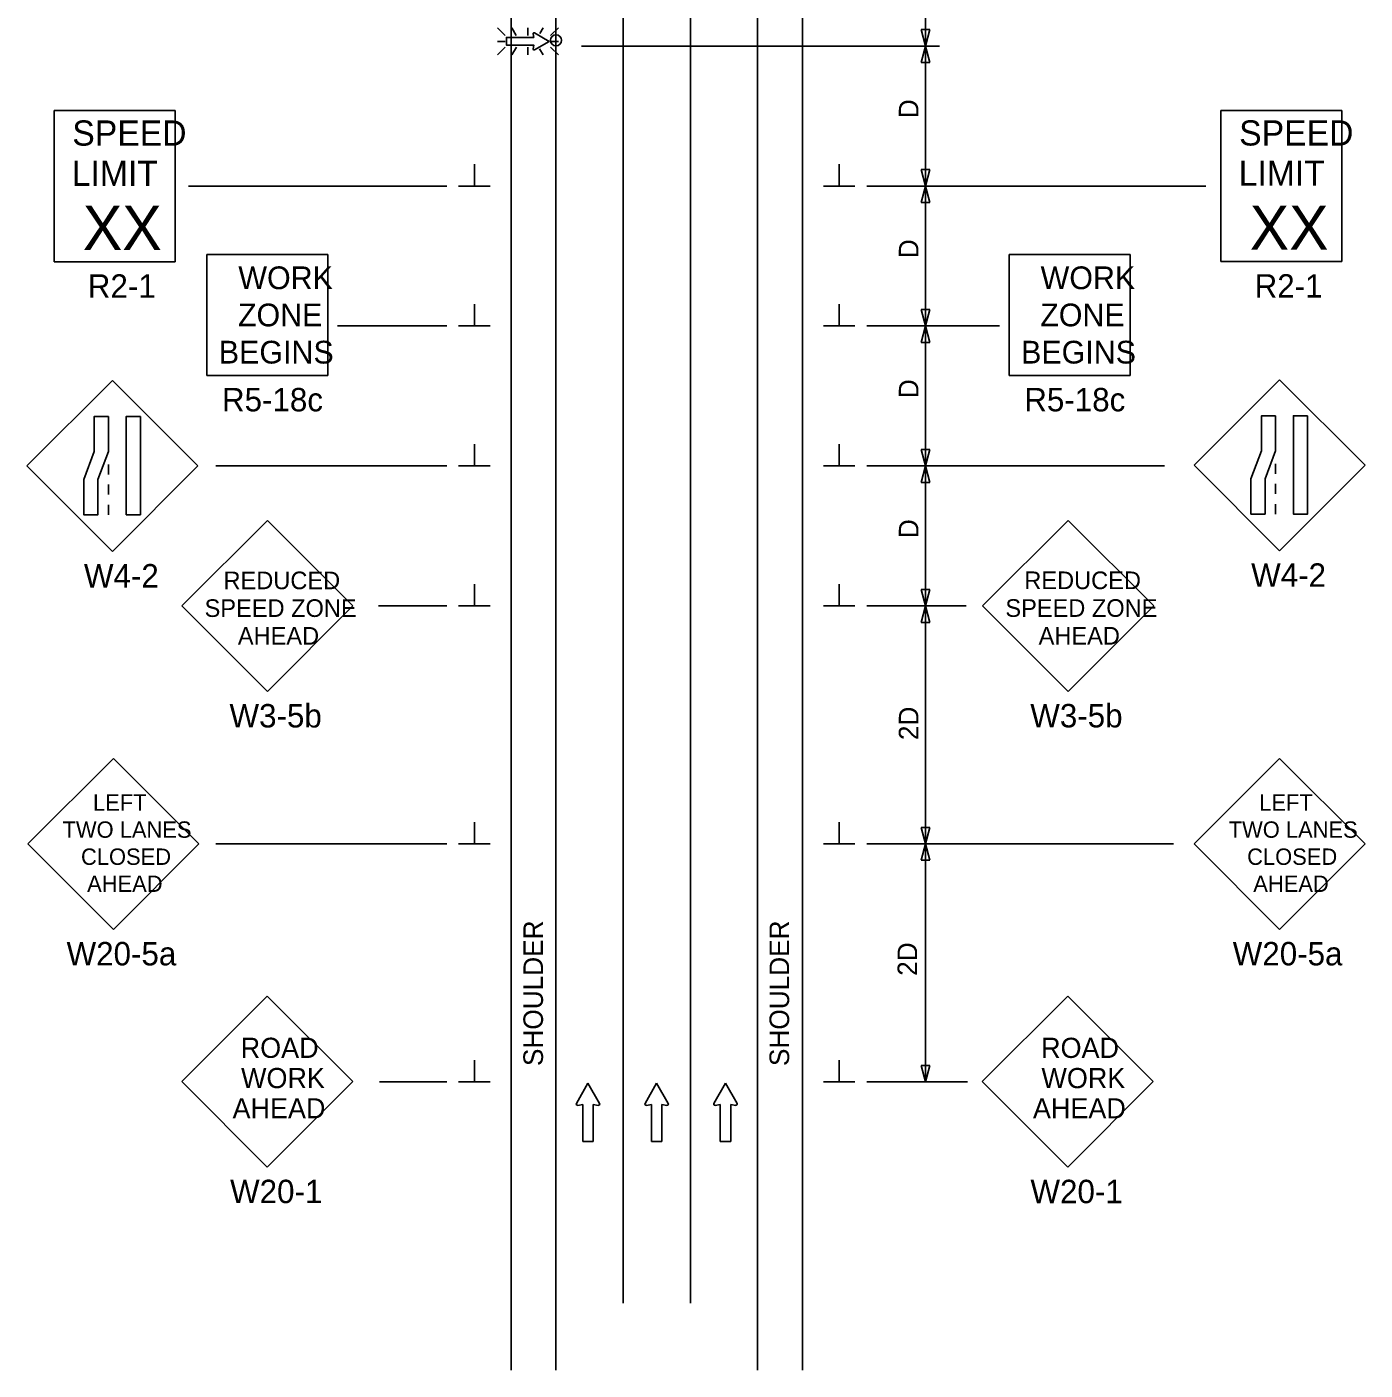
# Model space of a CAD drawing. Extents: x 16735 to 18480, y 5523 to 6928.
# Drawn here: x 16743.7 to 17221.6, y 6059.8 to 6539.6 of the extents above; entities that cross this region are included whole.
import ezdxf

# ---------------------------------------------------------------- set-up
doc = ezdxf.new("R2010")
doc.units = 0
for name, color, linetype in [('ALI_LEGAL_EX', 7, 'Continuous'), ('MT_SCRATCH_LEVEL_E', 7, 'Continuous'), ('PAVT_EDGE_EX', 7, 'Continuous'), ('TRAFFIC_SIGNS_PR', 7, 'Continuous'), ('TYPICAL_TEXT_DIMEN_PR', 7, 'Continuous')]:
    doc.layers.add(name, color=color, linetype=linetype)

msp = doc.modelspace()

# ---------------------------------------------------------------- linework, layer by layer
at = {"layer": 'ALI_LEGAL_EX'}
for p, q in [((16956.63, 6927.83), (16956.63, 6083.69)), ((16980.63, 6927.83), (16980.63, 6083.69))]:
    msp.add_line(p, q, dxfattribs=at)
for points in [[(16956.63, 6527.83), (16956.63, 6502.83)], [(16980.63, 6527.83), (16980.63, 6502.83)], [(16956.63, 6427.83), (16956.63, 6402.83)], [(16980.63, 6427.83), (16980.63, 6402.83)], [(16956.63, 6327.83), (16956.63, 6302.83)], [(16980.63, 6327.83), (16980.63, 6302.83)], [(16956.63, 6227.83), (16956.63, 6202.83)], [(16980.63, 6227.83), (16980.63, 6202.83)], [(16956.63, 6127.83), (16956.63, 6102.83)], [(16980.63, 6127.83), (16980.63, 6102.83)]]:
    msp.add_lwpolyline(points, dxfattribs=at)
at = {"layer": 'MT_SCRATCH_LEVEL_E'}
for p, q in [((16944.07, 6162.28), (16939.96, 6155.04)), ((16948.22, 6155.04), (16944.07, 6162.28)), ((16968.6, 6162.28), (16964.49, 6155.04)), ((16972.75, 6155.04), (16968.6, 6162.28)), ((16993.16, 6162.28), (16989.05, 6155.04)), ((16997.31, 6155.04), (16993.16, 6162.28)), ((16940.44, 6154.36), (16942.22, 6154.67)), ((16942.22, 6154.67), (16942.22, 6141.42)), ((16945.96, 6141.42), (16945.96, 6154.67)), ((16945.96, 6154.67), (16947.74, 6154.36)), ((16964.97, 6154.36), (16966.75, 6154.67)), ((16966.75, 6154.67), (16966.75, 6141.42)), ((16970.49, 6141.42), (16970.49, 6154.67)), ((16970.49, 6154.67), (16972.27, 6154.36)), ((16989.53, 6154.36), (16991.31, 6154.67)), ((16991.31, 6154.67), (16991.31, 6141.42)), ((16995.05, 6141.42), (16995.05, 6154.67)), ((16995.05, 6154.67), (16996.83, 6154.36)), ((16942.22, 6141.42), (16945.96, 6141.42)), ((16966.75, 6141.42), (16970.49, 6141.42)), ((16991.31, 6141.42), (16995.05, 6141.42))]:
    msp.add_line(p, q, dxfattribs=at)
for centre, start, end in [((16940.37, 6154.82), 150.4248, 279.9638), ((16947.81, 6154.82), 260.0362, 29.7731), ((16964.9, 6154.82), 150.4248, 279.9638), ((16972.34, 6154.82), 260.0362, 29.7731), ((16989.46, 6154.82), 150.4248, 279.9638), ((16996.9, 6154.82), 260.0362, 29.7731)]:
    msp.add_arc(centre, 0.463, start, end, dxfattribs=at)
at = {"layer": 'PAVT_EDGE_EX'}
for p, q in [((16916.63, 6919.19), (16916.63, 6059.77)), ((16932.63, 6919.19), (16932.63, 6059.77)), ((17004.63, 6919.19), (17004.63, 6059.77)), ((17020.63, 6919.19), (17020.63, 6059.77))]:
    msp.add_line(p, q, dxfattribs=at)
at = {"layer": 'TRAFFIC_SIGNS_PR'}
for p, q in [((16914.54, 6536.48), (16911.72, 6539.3)), ((16916.83, 6539.3), (16918.46, 6536.48)), ((16922.62, 6536.48), (16922.62, 6539.3)), ((16928.09, 6539.3), (16926.88, 6537.2)), ((16933.53, 6539.29), (16930.71, 6536.48)), ((16914.54, 6534.44), (16911.72, 6534.44)), ((16914.54, 6532.41), (16911.72, 6529.59)), ((16918.49, 6532.41), (16916.86, 6529.59)), ((16922.62, 6532.41), (16922.62, 6529.59)), ((16926.8, 6531.78), (16928.06, 6529.59)), ((16930.71, 6534.44), (16933.53, 6534.44)), ((16933.53, 6529.59), (16930.71, 6532.41)), ((16753.42, 6509.72), (16796.62, 6509.72)), ((16753.42, 6455.72), (16753.42, 6509.72)), ((16796.62, 6455.72), (16796.62, 6509.72)), ((17170.15, 6509.76), (17213.35, 6509.76)), ((17170.15, 6455.76), (17170.15, 6509.76)), ((17213.35, 6455.76), (17213.35, 6509.76)), ((16753.42, 6455.72), (16796.62, 6455.72)), ((16807.95, 6415.13), (16807.95, 6458.33)), ((16807.95, 6458.33), (16851.15, 6458.33)), ((16851.15, 6415.13), (16851.15, 6458.33)), ((17094.48, 6415.13), (17094.48, 6458.33)), ((17094.48, 6458.33), (17137.68, 6458.33)), ((17137.68, 6415.13), (17137.68, 6458.33)), ((17170.15, 6455.76), (17213.35, 6455.76)), ((16774.23, 6413.3), (16743.68, 6382.76)), ((16804.78, 6382.76), (16774.23, 6413.3)), ((16807.95, 6415.13), (16851.15, 6415.13)), ((17094.48, 6415.13), (17137.68, 6415.13)), ((17191.08, 6413.56), (17160.53, 6383.01)), ((17221.62, 6383.01), (17191.08, 6413.56)), ((16743.68, 6382.76), (16774.23, 6352.21)), ((16772.83, 6383.31), (16772.83, 6379.71)), ((16774.23, 6352.21), (16804.78, 6382.76)), ((17160.53, 6383.01), (17191.08, 6352.47)), ((17189.67, 6383.57), (17189.67, 6379.97)), ((17191.08, 6352.47), (17221.62, 6383.01)), ((16772.83, 6376.11), (16772.83, 6372.51)), ((17189.67, 6376.37), (17189.67, 6372.77)), ((16772.83, 6368.91), (16772.83, 6365.31)), ((17189.67, 6369.17), (17189.67, 6365.57)), ((16829.6, 6363.3), (16799.05, 6332.76)), ((16860.15, 6332.76), (16829.6, 6363.3)), ((17115.58, 6363.33), (17085.03, 6332.79)), ((17146.13, 6332.79), (17115.58, 6363.33)), ((16799.05, 6332.76), (16829.6, 6302.21)), ((16829.6, 6302.21), (16860.15, 6332.76)), ((17085.03, 6332.79), (17115.58, 6302.24)), ((17115.58, 6302.24), (17146.13, 6332.79)), ((16774.58, 6278.31), (16744.03, 6247.76)), ((16805.13, 6247.76), (16774.58, 6278.31)), ((17191.06, 6278.31), (17160.51, 6247.76)), ((17221.61, 6247.76), (17191.06, 6278.31)), ((16744.03, 6247.76), (16774.58, 6217.21)), ((16774.58, 6217.21), (16805.13, 6247.76)), ((17160.51, 6247.76), (17191.06, 6217.21)), ((17191.06, 6217.21), (17221.61, 6247.76)), ((16829.56, 6193.38), (16799.01, 6162.83)), ((16860.11, 6162.83), (16829.56, 6193.38)), ((17115.41, 6193.37), (17084.87, 6162.82)), ((17145.96, 6162.82), (17115.41, 6193.37)), ((16799.01, 6162.83), (16829.56, 6132.28)), ((16829.56, 6132.28), (16860.11, 6162.83)), ((17084.87, 6162.82), (17115.41, 6132.27)), ((17115.41, 6132.27), (17145.96, 6162.82))]:
    msp.add_line(p, q, dxfattribs=at)
for points in [[(16924.45, 6537.12), (16924.68, 6535.83), (16914.96, 6535.83), (16914.96, 6533.09), (16924.68, 6533.09), (16924.45, 6531.78)], [(16924.95, 6531.43), (16930.26, 6534.44), (16924.95, 6537.48)]]:
    msp.add_lwpolyline(points, dxfattribs=at)
for points in [[(16772.83, 6400.46), (16772.83, 6387.88), (16769.06, 6377.89), (16769.06, 6365.31), (16764.01, 6365.31), (16764.01, 6377.89), (16767.77, 6387.88), (16767.77, 6400.46)], [(16784.23, 6400.46), (16784.23, 6365.31), (16779.18, 6365.31), (16779.18, 6400.46)], [(17189.67, 6400.72), (17189.67, 6388.14), (17185.91, 6378.15), (17185.91, 6365.57), (17180.86, 6365.57), (17180.86, 6378.15), (17184.62, 6388.14), (17184.62, 6400.72)], [(17201.08, 6400.72), (17201.08, 6365.57), (17196.02, 6365.57), (17196.02, 6400.72)]]:
    msp.add_lwpolyline(points, close=True, dxfattribs=at)
msp.add_circle((16932.64, 6534.81), 2, dxfattribs=at)
for centre, start, end in [((16924.78, 6537.18), 61.4833, 189.9593), ((16924.78, 6531.73), 170.7308, 298.8916)]:
    msp.add_arc(centre, 0.341, start, end, dxfattribs=at)
at = {"layer": 'TYPICAL_TEXT_DIMEN_PR'}
for p, q in [((17064.63, 6532.76), (17064.63, 6563.32)), ((17064.63, 6532.76), (17063.06, 6538.62)), ((17063.06, 6538.62), (17064.63, 6538.62)), ((17064.63, 6538.62), (17066.2, 6538.62)), ((17066.2, 6538.62), (17064.63, 6532.76)), ((16941.8, 6532.76), (17069.63, 6532.76)), ((17063.06, 6526.9), (17064.63, 6532.76)), ((17064.63, 6532.76), (17064.63, 6482.76)), ((17064.63, 6532.76), (17066.2, 6526.9)), ((17064.63, 6526.9), (17063.06, 6526.9)), ((17066.2, 6526.9), (17064.63, 6526.9)), ((16903.51, 6482.76), (16903.51, 6490.55)), ((17033.76, 6482.76), (17033.76, 6490.55)), ((17064.63, 6482.76), (17063.06, 6488.62)), ((17063.06, 6488.62), (17064.63, 6488.62)), ((17064.63, 6488.62), (17066.2, 6488.62)), ((17066.2, 6488.62), (17064.63, 6482.76)), ((16801.4, 6482.76), (16893.63, 6482.76)), ((16897.88, 6482.76), (16909.13, 6482.76)), ((17039.38, 6482.76), (17028.13, 6482.76)), ((17043.63, 6482.76), (17164.68, 6482.76)), ((17063.06, 6476.9), (17064.63, 6482.76)), ((17064.63, 6482.76), (17064.63, 6432.76)), ((17064.63, 6482.76), (17066.2, 6476.9)), ((17064.63, 6476.9), (17063.06, 6476.9)), ((17066.2, 6476.9), (17064.63, 6476.9)), ((16903.51, 6432.76), (16903.51, 6440.55)), ((17033.76, 6432.76), (17033.76, 6440.55)), ((17064.63, 6432.76), (17063.06, 6438.62)), ((17063.06, 6438.62), (17064.63, 6438.62)), ((17064.63, 6438.62), (17066.2, 6438.62)), ((17066.2, 6438.62), (17064.63, 6432.76)), ((16893.63, 6432.76), (16854.59, 6432.76)), ((16897.88, 6432.76), (16909.13, 6432.76)), ((17039.38, 6432.76), (17028.13, 6432.76)), ((17043.63, 6432.76), (17091, 6432.76)), ((17063.06, 6426.9), (17064.63, 6432.76)), ((17064.63, 6432.76), (17066.2, 6426.9)), ((17064.63, 6432.76), (17064.63, 6382.76)), ((17064.63, 6426.9), (17063.06, 6426.9)), ((17066.2, 6426.9), (17064.63, 6426.9)), ((16903.51, 6382.76), (16903.51, 6390.55)), ((17033.76, 6382.76), (17033.76, 6390.55)), ((17064.63, 6382.76), (17063.06, 6388.62)), ((17063.06, 6388.62), (17064.63, 6388.62)), ((17064.63, 6388.62), (17066.2, 6388.62)), ((17066.2, 6388.62), (17064.63, 6382.76)), ((16893.63, 6382.76), (16811.15, 6382.76)), ((16897.88, 6382.76), (16909.13, 6382.76)), ((17039.38, 6382.76), (17028.13, 6382.76)), ((17043.63, 6382.76), (17149.98, 6382.76)), ((17063.06, 6376.9), (17064.63, 6382.76)), ((17064.63, 6382.76), (17064.63, 6332.76)), ((17064.63, 6382.76), (17066.2, 6376.9)), ((17064.63, 6376.9), (17063.06, 6376.9)), ((17066.2, 6376.9), (17064.63, 6376.9)), ((16903.51, 6332.76), (16903.51, 6340.55)), ((17033.76, 6332.76), (17033.76, 6340.55)), ((17064.63, 6332.76), (17063.06, 6338.62)), ((17063.06, 6338.62), (17064.63, 6338.62)), ((17064.63, 6338.62), (17066.2, 6338.62)), ((17066.2, 6338.62), (17064.63, 6332.76)), ((16869.32, 6332.76), (16893.63, 6332.76)), ((16897.88, 6332.76), (16909.13, 6332.76)), ((17039.38, 6332.76), (17028.13, 6332.76)), ((17043.63, 6332.76), (17079.09, 6332.76)), ((17063.06, 6326.9), (17064.63, 6332.76)), ((17064.63, 6332.76), (17064.63, 6247.76)), ((17064.63, 6332.76), (17066.2, 6326.9)), ((17064.63, 6326.9), (17063.06, 6326.9)), ((17066.2, 6326.9), (17064.63, 6326.9)), ((16903.51, 6247.76), (16903.51, 6255.55)), ((17033.76, 6247.76), (17033.76, 6255.55)), ((17064.63, 6247.76), (17063.06, 6253.62)), ((17063.06, 6253.62), (17064.63, 6253.62)), ((17064.63, 6253.62), (17066.2, 6253.62)), ((17066.2, 6253.62), (17064.63, 6247.76)), ((16893.63, 6247.76), (16811.22, 6247.76)), ((16897.88, 6247.76), (16909.13, 6247.76)), ((17039.38, 6247.76), (17028.13, 6247.76)), ((17043.63, 6247.76), (17153.23, 6247.76)), ((17063.06, 6241.9), (17064.63, 6247.76)), ((17064.63, 6247.76), (17064.63, 6162.76)), ((17064.63, 6247.76), (17066.2, 6241.9)), ((17064.63, 6241.9), (17063.06, 6241.9)), ((17066.2, 6241.9), (17064.63, 6241.9)), ((16903.51, 6162.76), (16903.51, 6170.55)), ((17033.76, 6162.76), (17033.76, 6170.55)), ((17064.63, 6162.76), (17063.06, 6168.62)), ((17063.06, 6168.62), (17064.63, 6168.62)), ((17064.63, 6168.62), (17066.2, 6168.62)), ((17066.2, 6168.62), (17064.63, 6162.76)), ((16893.63, 6162.76), (16869.63, 6162.76)), ((16897.88, 6162.76), (16909.13, 6162.76)), ((17039.38, 6162.76), (17028.13, 6162.76)), ((17043.63, 6162.76), (17079.63, 6162.76))]:
    msp.add_line(p, q, dxfattribs=at)

# ---------------------------------------------------------------- texts
at = {"layer": 'TRAFFIC_SIGNS_PR'}
for s, height, p in [('SPEED', 9, (16759.91, 6497.19)), ('SPEED', 9, (17176.64, 6497.23)), ('LIMIT', 9, (16759.73, 6482.79)), ('LIMIT', 9, (17176.46, 6482.83)), ('XX', 15.785, (16763.68, 6459.94)), ('XX', 15.785, (17180.4, 6459.99)), ('WORK', 8.119, (16819.2, 6445.92)), ('WORK', 8.119, (17105.73, 6445.92)), ('R2-1', 8.37, (16765.44, 6442.85)), ('R2-1', 8.37, (17182.16, 6442.89)), ('ZONE', 8.119, (16819.07, 6432.64)), ('ZONE', 8.119, (17105.59, 6432.64)), ('BEGINS', 8.119, (16812.24, 6419.35)), ('BEGINS', 8.119, (17098.76, 6419.35)), ('R5-18c', 8.37, (16813.36, 6402.26)), ('R5-18c', 8.37, (17099.89, 6402.26)), ('W4-2', 8.37, (16764.06, 6339.34)), ('REDUCED', 6.3, (16813.91, 6338.73)), ('REDUCED', 6.3, (17099.9, 6338.76)), ('W4-2', 8.37, (17180.91, 6339.6)), ('SPEED ZONE', 6.3, (16807.15, 6328.83)), ('SPEED ZONE', 6.3, (17093.14, 6328.86)), ('AHEAD', 6.3, (16819.03, 6318.93)), ('AHEAD', 6.3, (17105.02, 6318.96)), ('W3-5b', 8.37, (16816.05, 6289.34)), ('W3-5b', 8.37, (17102.03, 6289.37)), ('LEFT', 5.85, (16767.31, 6259.61)), ('LEFT', 5.85, (17183.79, 6259.61)), ('TWO LANES', 5.85, (16756.42, 6249.94)), ('TWO LANES', 5.85, (17172.9, 6249.94)), ('CLOSED', 5.85, (16763.01, 6240.26)), ('CLOSED', 5.85, (17179.49, 6240.26)), ('AHEAD', 5.85, (16765.2, 6230.59)), ('AHEAD', 5.85, (17181.68, 6230.59)), ('W20-5a', 8.37, (16757.86, 6204.35)), ('W20-5a', 8.37, (17174.34, 6204.35)), ('ROAD', 7.2, (16820.05, 6171.31)), ('ROAD', 7.2, (17105.9, 6171.3)), ('WORK', 7.2, (16820.17, 6160.51)), ('WORK', 7.2, (17106.02, 6160.5)), ('AHEAD', 7.2, (16817.14, 6149.71)), ('AHEAD', 7.2, (17102.99, 6149.7)), ('W20-1', 8.37, (16816.25, 6119.42)), ('W20-1', 8.37, (17102.1, 6119.4))]:
    msp.add_text(s, height=height, dxfattribs=at).set_placement(p)
at = {"layer": 'TYPICAL_TEXT_DIMEN_PR'}
for s, p in [('D', (17062.08, 6506.98)), ('D', (17062.08, 6456.98)), ('D', (17062.08, 6406.98)), ('D', (17062.08, 6356.98)), ('2D', (17062.08, 6284.83)), ('SHOULDER', (16928.01, 6168.39)), ('SHOULDER', (17015.91, 6168.39)), ('2D', (17061.64, 6200.62))]:
    msp.add_text(s, height=7, rotation=90, dxfattribs=at).set_placement(p)

doc.saveas('drawing.dxf')
